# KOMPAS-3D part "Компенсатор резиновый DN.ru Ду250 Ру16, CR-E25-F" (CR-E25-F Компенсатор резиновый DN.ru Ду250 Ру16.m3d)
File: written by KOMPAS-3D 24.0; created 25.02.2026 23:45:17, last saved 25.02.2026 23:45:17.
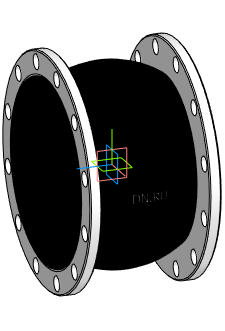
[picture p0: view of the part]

Document properties: Автор: DN.RU; Полное имя файла: D:\PROJECT CAD\DN.RU\...178(4)(ACTUALE). CR-E25-F Компенсатор резиновый DN.ru Ру10-16\DN250_PN16\CR-E25-F Компенсатор резиновый DN.ru Ду250 Ру16.m3d

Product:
- Body: Твердое тело2  | qty 1
    Масса: 65.214164
- Part/product: Компенсатор резиновый DN.ru Ду250 Ру16  | designation CR-E25-F
    Масса: 26.25
    Раздел спецификации: Прочие изделия
    Комментарий: D140-02180
    Примечание: D140-02180
    additional columns: Типовые

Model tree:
1. Твердое тело2  (labels: Твердое тело2)

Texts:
  CR-E25-F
